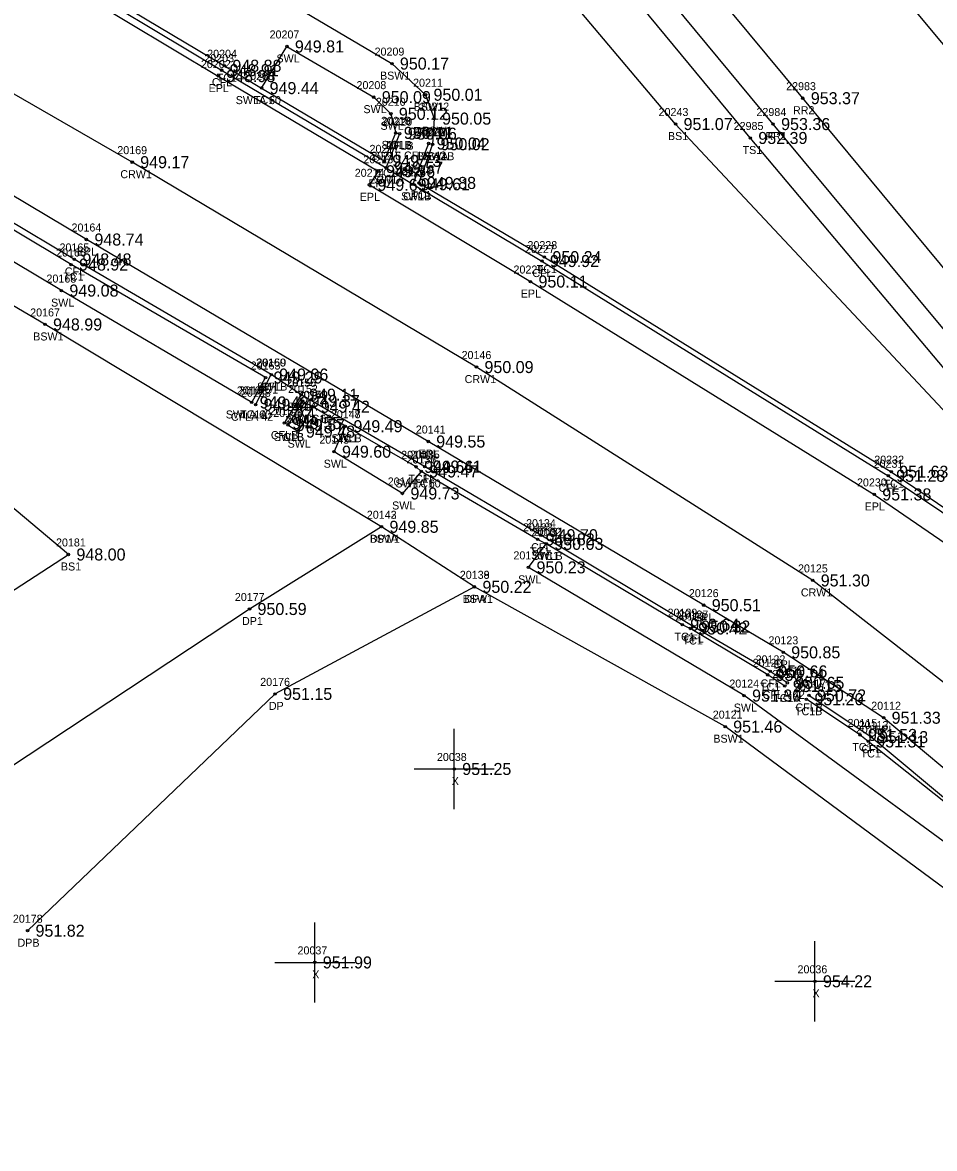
# Model space of a CAD drawing. Extents: x 1576181 to 1577685, y 1099396 to 1101490.
# Drawn here: x 1576239 to 1576353, y 1099602.5 to 1099743.2 of the extents above; entities that cross this region are included whole.
import ezdxf

# ---------------------------------------------------------------- set-up
doc = ezdxf.new("R2010")
doc.units = 0
for name, color, linetype in [('RD_DTM_BkLn1', 7, 'Continuous'), ('RD_DTM_BkLn2', 7, 'Continuous'), ('RD_DTM_BkLn_txCode', 7, 'Continuous'), ('RD_EX_Conc', 7, 'Continuous'), ('RD_EX_Conc_txCode', 7, 'Continuous'), ('RD_EX_Driveway', 7, 'Continuous'), ('RD_EX_Driveway_txCode', 7, 'Continuous'), ('RD_EX_Misc', 7, 'Continuous'), ('RD_EX_Misc_txCode', 7, 'Continuous'), ('RD_EX_RailRoad', 7, 'Continuous'), ('RD_EX_RailRoad_txCode', 7, 'Continuous'), ('RD_EX_Road', 7, 'Continuous'), ('RD_EX_Road_txCode', 7, 'Continuous'), ('RD_EX_TX_Conc_ELEV', 7, 'Continuous'), ('RD_EX_TX_Driveway_ELEV', 7, 'Continuous'), ('RD_EX_TX_Misc_ELEV', 7, 'Continuous'), ('RD_EX_TX_RailRoad_ELEV', 7, 'Continuous'), ('RD_EX_TX_Road_ELEV', 7, 'Continuous'), ('RD_HC_Survey_ELEV', 7, 'Continuous'), ('RD_HC_Survey_txCode', 7, 'Continuous'), ('RD_SMD_Locator', 7, 'Continuous')]:
    doc.layers.add(name, color=color, linetype=linetype)

msp = doc.modelspace()

# ---------------------------------------------------------------- linework, layer by layer
at = {"layer": 'RD_DTM_BkLn1'}
msp.add_lwpolyline([(1576411.06, 1099606.41), (1576377.33, 1099642.66), (1576337.77, 1099673.47), (1576295.75, 1099700.12), (1576252.73, 1099725.71), (1576209.23, 1099750.79)], dxfattribs=at)
at = {"layer": 'RD_DTM_BkLn2'}
for points in [[(1576271.23, 1099836.06), (1576304.3, 1099797.36), (1576339.24, 1099758.21), (1576368.71, 1099722.87), (1576388.13, 1099699.72), (1576412.66, 1099672.77), (1576428.35, 1099666.09)], [(1576397.55, 1099648.8), (1576363.44, 1099688.93), (1576329.97, 1099728.73), (1576294.41, 1099771.72), (1576252.83, 1099822.18)], [(1576386.37, 1099656.97), (1576355.23, 1099693.54), (1576320.63, 1099730.47), (1576281, 1099777.41)], [(1576218.46, 1099765.13), (1576219.9, 1099764.24), (1576224.13, 1099761.71), (1576238.11, 1099753.29), (1576242.76, 1099750.55), (1576264.25, 1099737.75), (1576268.9, 1099734.96), (1576284.22, 1099725.87), (1576285.67, 1099729.37)], [(1576267.66, 1099695.7), (1576269.39, 1099698.81), (1576245.1, 1099712.92), (1576201.25, 1099739.16)], [(1576290.26, 1099727.95), (1576288.56, 1099723.12), (1576304.24, 1099713.85), (1576347.58, 1099687.05), (1576370.85, 1099671.31), (1576386.37, 1099656.97)], [(1576210.7, 1099654.61), (1576244.76, 1099676.71), (1576220.1, 1099697.42), (1576191.57, 1099723.35)], [(1576334.28, 1099660.28), (1576332.14, 1099661.68), (1576322.46, 1099667.47), (1576321.46, 1099667.94), (1576304.48, 1099678.04), (1576303.39, 1099678.6), (1576288.86, 1099687.08), (1576288.21, 1099687.66), (1576279.38, 1099692.73), (1576275.29, 1099695.16), (1576274.03, 1099695.88), (1576272.19, 1099692.88)], [(1576383.65, 1099614.47), (1576380.11, 1099618.44), (1576367.7, 1099632.52), (1576356.26, 1099643.84), (1576355.34, 1099644.92), (1576344.71, 1099653.36), (1576343.67, 1099654.17), (1576336.98, 1099658.63)]]:
    msp.add_lwpolyline(points, dxfattribs=at)
at = {"layer": 'RD_EX_Conc'}
for p, q in [((1576284.46, 1099725.02), (1576287.8, 1099722.95)), ((1576273.84, 1099696.67), (1576270.1, 1099699.18))]:
    msp.add_line(p, q, dxfattribs=at)
for points in [[(1576223.52, 1099774.79), (1576266.89, 1099748.86), (1576285.18, 1099738.02), (1576289.38, 1099734.13), (1576290.45, 1099731.15), (1576290.26, 1099727.95)], [(1576218.09, 1099764.57), (1576242.44, 1099750.07), (1576263.9, 1099737.2), (1576284.46, 1099725.02), (1576286.16, 1099729.27)], [(1576268.15, 1099695.41), (1576270.1, 1099699.18), (1576245.51, 1099713.56), (1576201.52, 1099739.77)], [(1576268.9, 1099734.96), (1576272.06, 1099740.16), (1576282.92, 1099733.83), (1576285.05, 1099731.75), (1576285.67, 1099729.37)], [(1576267.66, 1099695.7), (1576243.88, 1099709.67), (1576199.3, 1099736.28)], [(1576375.69, 1099614.26), (1576362.91, 1099628.6), (1576326.83, 1099655.21), (1576295.5, 1099672.67), (1576283.88, 1099680.17), (1576241.84, 1099705.44), (1576196.96, 1099731.78)], [(1576289.77, 1099728.04), (1576287.8, 1099722.95), (1576303.93, 1099713.36), (1576347.2, 1099686.54), (1576370.5, 1099670.91), (1576386.09, 1099656.79)], [(1576334.59, 1099660.68), (1576332.46, 1099662.11), (1576322.83, 1099667.71), (1576303.78, 1099679.12), (1576289.27, 1099687.69), (1576273.84, 1099696.67), (1576271.73, 1099693.12)], [(1576275.29, 1099695.16), (1576273.44, 1099692.05), (1576272.19, 1099692.88)], [(1576288.86, 1099687.08), (1576286.5, 1099684.33), (1576277.95, 1099689.55), (1576279.38, 1099692.73)], [(1576380.11, 1099618.44), (1576379.26, 1099617.75), (1576366.66, 1099631.69), (1576329.19, 1099659.09), (1576302.25, 1099675.1), (1576304.48, 1099678.04)], [(1576384, 1099614.83), (1576380.5, 1099618.86), (1576368.1, 1099632.86), (1576355.6, 1099645.12), (1576345.06, 1099653.9), (1576337.3, 1099659.11)]]:
    msp.add_lwpolyline(points, dxfattribs=at)
at = {"layer": 'RD_EX_Driveway'}
for points in [[(1576283.88, 1099680.17), (1576267.39, 1099669.9), (1576224.57, 1099641.63)], [(1576295.5, 1099672.67), (1576270.59, 1099659.3), (1576239.65, 1099629.72)]]:
    msp.add_lwpolyline(points, dxfattribs=at)
at = {"layer": 'RD_EX_Misc'}
for p, q in [((1576292.97, 1099644.92), (1576292.97, 1099654.92)), ((1576287.97, 1099649.92), (1576297.97, 1099649.92)), ((1576275.55, 1099620.76), (1576275.55, 1099630.76)), ((1576338.05, 1099618.4), (1576338.05, 1099628.4)), ((1576270.55, 1099625.76), (1576280.55, 1099625.76)), ((1576333.05, 1099623.4), (1576343.05, 1099623.4))]:
    msp.add_line(p, q, dxfattribs=at)
at = {"layer": 'RD_EX_RailRoad'}
for points in [[(1576588.64, 1099429.74), (1576556.82, 1099468.27), (1576525.53, 1099505.93), (1576492.19, 1099546.33), (1576461.17, 1099583.65), (1576447.93, 1099599.71), (1576411.91, 1099642.96), (1576369.31, 1099694.21), (1576336.53, 1099733.7), (1576300.55, 1099777.04), (1576258.58, 1099827.59)], [(1576584.91, 1099426.47), (1576552.99, 1099465.14), (1576521.86, 1099502.63), (1576488.35, 1099543.2), (1576457.44, 1099580.52), (1576443.75, 1099596.96), (1576408.06, 1099639.92), (1576365.56, 1099691.12), (1576332.82, 1099730.47), (1576296.82, 1099773.87), (1576254.94, 1099824.3)]]:
    msp.add_lwpolyline(points, dxfattribs=at)
at = {"layer": 'RD_EX_Road'}
for points in [[(1576217.78, 1099763.81), (1576263.48, 1099736.46), (1576283.45, 1099724.57), (1576282.38, 1099722.88), (1576302.5, 1099710.8), (1576345.46, 1099684.21), (1576368.62, 1099668.36), (1576383.76, 1099654.94), (1576386.09, 1099656.79), (1576408.06, 1099639.92), (1576408.06, 1099639.92), (1576411.91, 1099642.96), (1576420.57, 1099654.58), (1576428.78, 1099665.98), (1576435.66, 1099661.47), (1576436.12, 1099661.14), (1576438.46, 1099659.42), (1576459.37, 1099692.41), (1576486.6, 1099735.59), (1576512.85, 1099776.73), (1576539.46, 1099818.98), (1576543.78, 1099825.47), (1576541.42, 1099827.15), (1576542.92, 1099831.85)], [(1576385.97, 1099603.2), (1576388.62, 1099605.88), (1576388.15, 1099611.28), (1576384.7, 1099615.46), (1576386.17, 1099616.78), (1576370.2, 1099635.03), (1576357.38, 1099647.31), (1576346.63, 1099656.32), (1576334.08, 1099664.49), (1576324.15, 1099670.38), (1576289.72, 1099690.82), (1576247.01, 1099716.05), (1576203, 1099742.27)]]:
    msp.add_lwpolyline(points, dxfattribs=at)
at = {"layer": 'RD_SMD_Locator'}
for centre in [(1576272.06, 1099740.16), (1576264.25, 1099737.75), (1576285.18, 1099738.02), (1576263.48, 1099736.46), (1576263.9, 1099737.2), (1576268.9, 1099734.96), (1576268.9, 1099734.96), (1576282.92, 1099733.83), (1576289.38, 1099734.13), (1576336.53, 1099733.7), (1576285.05, 1099731.75), (1576290.45, 1099731.15), (1576320.63, 1099730.47), (1576332.82, 1099730.47), (1576285.67, 1099729.37), (1576285.67, 1099729.37), (1576286.16, 1099729.27), (1576289.77, 1099728.04), (1576290.26, 1099727.95), (1576290.26, 1099727.95), (1576329.97, 1099728.73), (1576252.73, 1099725.71), (1576284.22, 1099725.87), (1576284.46, 1099725.02), (1576284.46, 1099725.02), (1576283.45, 1099724.57), (1576282.38, 1099722.88), (1576287.8, 1099722.95), (1576287.8, 1099722.95), (1576288.56, 1099723.12), (1576247.01, 1099716.05), (1576245.51, 1099713.56), (1576304.24, 1099713.85), (1576245.1, 1099712.92), (1576303.93, 1099713.36), (1576302.5, 1099710.8), (1576243.88, 1099709.67), (1576241.84, 1099705.44), (1576295.75, 1099700.12), (1576269.39, 1099698.81), (1576270.1, 1099699.18), (1576270.1, 1099699.18), (1576273.84, 1099696.67), (1576273.84, 1099696.67), (1576267.66, 1099695.7), (1576267.66, 1099695.7), (1576268.15, 1099695.41), (1576274.03, 1099695.88), (1576275.29, 1099695.16), (1576275.29, 1099695.16), (1576271.73, 1099693.12), (1576272.19, 1099692.88), (1576272.19, 1099692.88), (1576279.38, 1099692.73), (1576279.38, 1099692.73), (1576273.44, 1099692.05), (1576277.95, 1099689.55), (1576289.72, 1099690.82), (1576288.21, 1099687.66), (1576288.86, 1099687.08), (1576288.86, 1099687.08), (1576289.27, 1099687.69), (1576347.58, 1099687.05), (1576347.2, 1099686.54), (1576286.5, 1099684.33), (1576345.46, 1099684.21), (1576283.88, 1099680.17), (1576283.88, 1099680.17), (1576303.39, 1099678.6), (1576303.78, 1099679.12), (1576304.48, 1099678.04), (1576304.48, 1099678.04), (1576244.76, 1099676.71), (1576302.25, 1099675.1), (1576295.5, 1099672.67), (1576295.5, 1099672.67), (1576337.77, 1099673.47), (1576267.39, 1099669.9), (1576324.15, 1099670.38), (1576321.46, 1099667.94), (1576322.46, 1099667.47), (1576322.83, 1099667.71), (1576334.08, 1099664.49), (1576332.14, 1099661.68), (1576332.46, 1099662.11), (1576334.28, 1099660.28), (1576334.59, 1099660.68), (1576270.59, 1099659.3), (1576329.19, 1099659.09), (1576336.98, 1099658.63), (1576337.3, 1099659.11), (1576346.63, 1099656.32), (1576326.83, 1099655.21), (1576343.67, 1099654.17), (1576344.71, 1099653.36), (1576345.06, 1099653.9), (1576292.97, 1099649.92), (1576239.65, 1099629.72), (1576275.55, 1099625.76), (1576338.05, 1099623.4)]:
    msp.add_circle(centre, 0.15, dxfattribs=at)

# ---------------------------------------------------------------- texts
at = {"layer": 'RD_DTM_BkLn_txCode'}
for s, p in [('20243', (1576318.51, 1099731.47)), ('22985', (1576327.89, 1099729.73)), ('BS1', (1576319.68, 1099728.47)), ('TS1', (1576329.01, 1099726.73)), ('20181', (1576243.21, 1099677.71)), ('BS1', (1576243.82, 1099674.71))]:
    msp.add_text(s, height=1, dxfattribs=at).set_placement(p)
at = {"layer": 'RD_EX_Conc_txCode'}
for s, p in [('20207', (1576269.9, 1099741.16)), ('20203', (1576261.74, 1099738.2)), ('20204', (1576262.1, 1099738.75)), ('SWL', (1576270.76, 1099738.16)), ('20209', (1576283.02, 1099739.02)), ('CFL', (1576262.69, 1099735.2)), ('TC1', (1576263.29, 1099735.75)), ('20206', (1576266.72, 1099735.96)), ('20205', (1576266.74, 1099735.96)), ('BSW1', (1576283.7, 1099736.02)), ('20211', (1576287.83, 1099735.13)), ('20208', (1576280.76, 1099734.83)), ('SWLA 60', (1576265.67, 1099732.96)), ('TC1', (1576267.94, 1099732.96)), ('20210', (1576283.18, 1099732.75)), ('SWL', (1576281.63, 1099731.83)), ('BSW1', (1576287.9, 1099732.13)), ('20212', (1576288.62, 1099732.15)), ('SWL', (1576283.76, 1099729.75)), ('20218', (1576283.83, 1099730.37)), ('20219', (1576283.83, 1099730.37)), ('20220', (1576284, 1099730.27)), ('20221', (1576287.94, 1099729.04)), ('20222', (1576288.15, 1099728.95)), ('20223', (1576288.15, 1099728.95)), ('BSW1', (1576288.97, 1099729.15)), ('20217', (1576282.39, 1099726.87)), ('SWLB', (1576283.9, 1099727.37)), ('TC1B', (1576284.23, 1099727.37)), ('CFLB', (1576284.48, 1099727.27)), ('20216', (1576282.6, 1099726.02)), ('20215', (1576282.62, 1099726.02)), ('CFLA 42', (1576286.69, 1099726.04)), ('BSW1B', (1576288.31, 1099725.95)), ('TC1A', (1576288.81, 1099725.95)), ('TC1', (1576283.26, 1099723.87)), ('20226', (1576285.66, 1099723.95)), ('20225', (1576285.68, 1099723.95)), ('20224', (1576286.44, 1099724.12)), ('SW1A', (1576282.96, 1099723.02)), ('CFL', (1576283.25, 1099723.02)), ('TC1', (1576287.6, 1099721.12)), ('SW1B', (1576286.32, 1099720.95)), ('CFL', (1576286.59, 1099720.95)), ('20165', (1576243.65, 1099714.56)), ('20227', (1576301.82, 1099714.36)), ('20228', (1576302.12, 1099714.85)), ('20166', (1576243.22, 1099713.92)), ('CFL', (1576244.31, 1099711.56)), ('CFL', (1576302.73, 1099711.36)), ('TC1', (1576303.28, 1099711.85)), ('20168', (1576242.02, 1099710.67)), ('TC1', (1576244.14, 1099710.92)), ('SWL', (1576242.59, 1099707.67)), ('20167', (1576239.98, 1099706.44)), ('BSW1', (1576240.36, 1099703.44)), ('20160', (1576268.2, 1099700.18)), ('20159', (1576268.26, 1099700.18)), ('20163', (1576267.53, 1099699.81)), ('SWLB', (1576268.33, 1099697.18)), ('CFL', (1576268.89, 1099697.18)), ('20156', (1576271.98, 1099697.67)), ('20155', (1576272.01, 1099697.67)), ('20162', (1576265.8, 1099696.7)), ('20161', (1576266.08, 1099696.7)), ('20158', (1576266.32, 1099696.41)), ('TC1', (1576268.43, 1099696.81)), ('20152', (1576272.2, 1099696.88)), ('20150', (1576273.41, 1099696.16)), ('20149', (1576273.45, 1099696.16)), ('SWLA', (1576272.06, 1099694.67)), ('CFL', (1576272.64, 1099694.67)), ('SWLA 60', (1576264.43, 1099693.7)), ('CFLA 42', (1576265.07, 1099693.41)), ('TC1A', (1576266.21, 1099693.7)), ('20157', (1576269.9, 1099694.12)), ('20153', (1576270.36, 1099693.88)), ('20154', (1576270.36, 1099693.88)), ('20151', (1576271.89, 1099693.05)), ('SWLA 60', (1576272.06, 1099693.16)), ('TC1', (1576273.07, 1099693.88)), ('TC1', (1576274.33, 1099693.16)), ('20147', (1576277.55, 1099693.73)), ('20148', (1576277.55, 1099693.73)), ('CFLB', (1576270.06, 1099691.12)), ('SWLB', (1576270.43, 1099690.88)), ('TC1B', (1576270.76, 1099690.88)), ('SWL', (1576272.15, 1099690.05)), ('20145', (1576276.12, 1099690.55)), ('SWLB', (1576277.62, 1099690.73)), ('TC1', (1576278.42, 1099690.73)), ('20140', (1576286.34, 1099688.66)), ('20135', (1576287.44, 1099688.69)), ('SWL', (1576276.66, 1099687.55)), ('20136', (1576287, 1099688.08)), ('20137', (1576287.03, 1099688.08)), ('20231', (1576345.37, 1099687.54)), ('20232', (1576345.46, 1099688.05)), ('20144', (1576284.66, 1099685.33)), ('SWLA 60', (1576285.63, 1099685.08)), ('TC1', (1576287.25, 1099685.66)), ('TC1', (1576287.9, 1099685.08)), ('CFL', (1576288.07, 1099685.69)), ('CFL', (1576346, 1099684.54)), ('TC1', (1576346.62, 1099685.05)), ('SWL', (1576285.21, 1099682.33)), ('20142', (1576282.05, 1099681.17)), ('20133', (1576301.56, 1099679.6)), ('20134', (1576301.95, 1099680.12)), ('20132', (1576302.64, 1099679.04)), ('20131', (1576302.93, 1099679.04)), ('BSW1', (1576282.4, 1099678.17)), ('20130', (1576300.37, 1099676.1)), ('TC1', (1576302.43, 1099676.6)), ('CFL', (1576302.58, 1099677.12)), ('SWLB', (1576302.72, 1099676.04)), ('TC1', (1576303.52, 1099676.04)), ('20138', (1576293.67, 1099673.67)), ('SWL', (1576300.96, 1099673.1)), ('BSW1', (1576294.02, 1099670.67)), ('20129', (1576319.63, 1099668.94)), ('20128', (1576320.63, 1099668.47)), ('20127', (1576321, 1099668.71)), ('TC1', (1576320.5, 1099665.94)), ('TC1', (1576321.5, 1099665.47)), ('CFL', (1576321.63, 1099665.71)), ('20120', (1576330.27, 1099662.68)), ('20122', (1576330.63, 1099663.11)), ('20119', (1576332.73, 1099661.28)), ('20118', (1576333.04, 1099661.68)), ('20124', (1576327.35, 1099660.09)), ('TC1', (1576331.18, 1099659.68)), ('CFL', (1576331.26, 1099660.11)), ('20116', (1576335.41, 1099659.63)), ('20117', (1576335.74, 1099660.11)), ('CFLA 42', (1576331.51, 1099658.68)), ('TC1A', (1576332.84, 1099658.28)), ('SWL', (1576327.9, 1099657.09)), ('TC1B', (1576335.55, 1099656.63)), ('CFLB', (1576335.62, 1099657.11)), ('20121', (1576325.28, 1099656.21)), ('20115', (1576342.12, 1099655.17)), ('20113', (1576343.51, 1099654.9)), ('20114', (1576343.16, 1099654.36)), ('BSW1', (1576325.35, 1099653.21)), ('TC1', (1576342.71, 1099652.17)), ('TC1', (1576343.75, 1099651.36)), ('CFL', (1576343.86, 1099651.9))]:
    msp.add_text(s, height=1, dxfattribs=at).set_placement(p)
at = {"layer": 'RD_EX_Driveway_txCode'}
for s, p in [('20143', (1576282.05, 1099681.17)), ('DP1A', (1576282.45, 1099678.17)), ('20139', (1576293.67, 1099673.67)), ('20177', (1576265.56, 1099670.9)), ('DPA', (1576294.24, 1099670.67)), ('DP1', (1576266.45, 1099667.9)), ('20176', (1576268.73, 1099660.3)), ('DP', (1576269.81, 1099657.3)), ('20178', (1576237.82, 1099630.72)), ('DPB', (1576238.4, 1099627.72))]:
    msp.add_text(s, height=1, dxfattribs=at).set_placement(p)
at = {"layer": 'RD_EX_Misc_txCode'}
for s, p in [('20038', (1576290.81, 1099650.92)), ('X', (1576292.66, 1099647.92)), ('20037', (1576273.39, 1099626.76)), ('20036', (1576335.87, 1099624.4)), ('X', (1576275.23, 1099623.76)), ('X', (1576337.74, 1099621.4))]:
    msp.add_text(s, height=1, dxfattribs=at).set_placement(p)
at = {"layer": 'RD_EX_RailRoad_txCode'}
for s, p in [('22983', (1576334.45, 1099734.7)), ('22984', (1576330.74, 1099731.47)), ('RR2', (1576335.3, 1099731.7)), ('RR1', (1576331.87, 1099728.47))]:
    msp.add_text(s, height=1, dxfattribs=at).set_placement(p)
at = {"layer": 'RD_EX_Road_txCode'}
for s, p in [('20202', (1576261.32, 1099737.46)), ('EPL', (1576262.28, 1099734.46)), ('20213', (1576281.62, 1099725.57)), ('20214', (1576280.54, 1099723.88)), ('EPL', (1576282.25, 1099722.57)), ('EPL', (1576281.17, 1099720.88)), ('20164', (1576245.15, 1099717.05)), ('EPL', (1576245.8, 1099714.05)), ('20229', (1576300.38, 1099711.8)), ('EPL', (1576301.29, 1099708.8)), ('20141', (1576288.17, 1099691.82)), ('EPL', (1576288.52, 1099688.82)), ('20230', (1576343.3, 1099685.21)), ('EPL', (1576344.26, 1099682.21)), ('20126', (1576322.29, 1099671.38)), ('EPL', (1576322.94, 1099668.38)), ('20123', (1576332.24, 1099665.49)), ('EPL', (1576332.87, 1099662.49)), ('20112', (1576345.08, 1099657.32)), ('EPL', (1576345.43, 1099654.32))]:
    msp.add_text(s, height=1, dxfattribs=at).set_placement(p)
at = {"layer": 'RD_EX_TX_Conc_ELEV'}
for s, p in [('949.81', (1576273.06, 1099739.41)), ('948.91', (1576264.9, 1099736.45)), ('948.88', (1576265.25, 1099737)), ('950.17', (1576286.18, 1099737.27)), ('949.44', (1576269.9, 1099734.21)), ('949.44', (1576269.9, 1099734.21)), ('950.01', (1576290.38, 1099733.38)), ('950.09', (1576283.92, 1099733.08)), ('950.12', (1576286.05, 1099731)), ('950.05', (1576291.45, 1099730.4)), ('950.11', (1576286.67, 1099728.62)), ('950.11', (1576286.67, 1099728.62)), ('950.06', (1576287.16, 1099728.52)), ('950.04', (1576290.77, 1099727.29)), ('950.02', (1576291.26, 1099727.2)), ('950.02', (1576291.26, 1099727.2)), ('949.73', (1576285.22, 1099725.12)), ('949.57', (1576285.46, 1099724.27)), ('949.57', (1576285.46, 1099724.27)), ('949.61', (1576288.8, 1099722.2)), ('949.61', (1576288.8, 1099722.2)), ('949.88', (1576289.56, 1099722.37)), ('948.92', (1576246.1, 1099712.17)), ('948.48', (1576246.51, 1099712.81)), ('949.92', (1576304.93, 1099712.61)), ('950.24', (1576305.24, 1099713.1)), ('949.08', (1576244.88, 1099708.92)), ('948.99', (1576242.84, 1099704.69)), ('949.29', (1576270.39, 1099698.06)), ('949.06', (1576271.1, 1099698.43)), ('949.06', (1576271.1, 1099698.43)), ('949.11', (1576274.84, 1099695.92)), ('949.11', (1576274.84, 1099695.92)), ('949.42', (1576268.66, 1099694.95)), ('949.42', (1576268.66, 1099694.95)), ('949.44', (1576269.15, 1099694.66)), ('949.37', (1576275.03, 1099695.13)), ('949.42', (1576276.29, 1099694.41)), ('949.42', (1576276.29, 1099694.41)), ('949.55', (1576272.73, 1099692.37)), ('949.57', (1576273.19, 1099692.13)), ('949.57', (1576273.19, 1099692.13)), ('949.48', (1576274.44, 1099691.3)), ('949.49', (1576280.38, 1099691.98)), ('949.49', (1576280.38, 1099691.98)), ('949.60', (1576278.95, 1099688.8)), ('949.66', (1576289.21, 1099686.91)), ('949.41', (1576290.27, 1099686.94)), ('949.47', (1576289.86, 1099686.33)), ('949.47', (1576289.86, 1099686.33)), ('951.28', (1576348.2, 1099685.79)), ('951.63', (1576348.58, 1099686.3)), ('949.73', (1576287.5, 1099683.58)), ('949.85', (1576284.88, 1099679.42)), ('949.70', (1576304.78, 1099678.37)), ('949.82', (1576304.39, 1099677.85)), ('950.03', (1576305.48, 1099677.29)), ('950.03', (1576305.48, 1099677.29)), ('950.23', (1576303.25, 1099674.35)), ('950.22', (1576296.5, 1099671.92)), ('950.64', (1576322.46, 1099667.19)), ('950.42', (1576323.46, 1099666.72)), ('950.32', (1576323.83, 1099666.96)), ('950.74', (1576333.14, 1099660.93)), ('950.66', (1576333.46, 1099661.36)), ('951.15', (1576335.28, 1099659.53)), ('950.65', (1576335.59, 1099659.93)), ('951.30', (1576330.19, 1099658.34)), ('951.20', (1576337.98, 1099657.88)), ('950.72', (1576338.3, 1099658.36)), ('951.46', (1576327.83, 1099654.46)), ('951.53', (1576344.67, 1099653.42)), ('951.13', (1576346.06, 1099653.15)), ('951.31', (1576345.71, 1099652.61))]:
    msp.add_text(s, height=1.5, dxfattribs=at).set_placement(p)
at = {"layer": 'RD_EX_TX_Driveway_ELEV'}
for s, p in [('949.85', (1576284.88, 1099679.42)), ('950.22', (1576296.5, 1099671.92)), ('950.59', (1576268.39, 1099669.15)), ('951.15', (1576271.59, 1099658.55)), ('951.82', (1576240.65, 1099628.97))]:
    msp.add_text(s, height=1.5, dxfattribs=at).set_placement(p)
at = {"layer": 'RD_EX_TX_Misc_ELEV'}
for s, p in [('951.07', (1576321.63, 1099729.72)), ('952.39', (1576330.97, 1099727.98)), ('948.00', (1576245.76, 1099675.96)), ('951.25', (1576293.97, 1099649.17)), ('951.99', (1576276.55, 1099625.01)), ('954.22', (1576339.05, 1099622.65))]:
    msp.add_text(s, height=1.5, dxfattribs=at).set_placement(p)
at = {"layer": 'RD_EX_TX_RailRoad_ELEV'}
for s, p in [('953.37', (1576337.53, 1099732.95)), ('953.36', (1576333.82, 1099729.72))]:
    msp.add_text(s, height=1.5, dxfattribs=at).set_placement(p)
at = {"layer": 'RD_EX_TX_Road_ELEV'}
for s, p in [('948.98', (1576264.48, 1099735.71)), ('949.56', (1576284.45, 1099723.82)), ('949.69', (1576283.38, 1099722.13)), ('948.74', (1576248.01, 1099715.3)), ('950.11', (1576303.5, 1099710.05)), ('949.55', (1576290.72, 1099690.07)), ('951.38', (1576346.46, 1099683.46)), ('950.51', (1576325.15, 1099669.63)), ('950.85', (1576335.08, 1099663.74)), ('951.33', (1576347.63, 1099655.57))]:
    msp.add_text(s, height=1.5, dxfattribs=at).set_placement(p)
at = {"layer": 'RD_HC_Survey_ELEV'}
for s, p in [('949.17', (1576253.73, 1099724.96)), ('950.09', (1576296.75, 1099699.37)), ('951.30', (1576338.77, 1099672.72))]:
    msp.add_text(s, height=1.5, dxfattribs=at).set_placement(p)
at = {"layer": 'RD_HC_Survey_txCode'}
for s, p in [('20169', (1576250.87, 1099726.71)), ('CRW1', (1576251.25, 1099723.71)), ('20146', (1576293.89, 1099701.12)), ('CRW1', (1576294.27, 1099698.12)), ('20125', (1576335.93, 1099674.47)), ('CRW1', (1576336.29, 1099671.47))]:
    msp.add_text(s, height=1, dxfattribs=at).set_placement(p)

doc.saveas('drawing.dxf')
